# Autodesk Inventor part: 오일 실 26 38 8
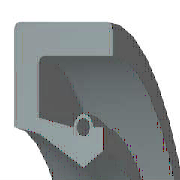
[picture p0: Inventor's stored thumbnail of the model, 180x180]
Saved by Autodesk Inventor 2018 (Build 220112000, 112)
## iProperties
IsCustomPart: 1
Created: 2012-02
Part Number: 오일 실 26 38 8
Material: 고무
Description: 오일-실
Document SubType Name: Modeling
Standard: KS B 2804
Designer: mduedu
Standards Organization: KS
Language: ko-KR
Size Designation: S - 26 38 8
Categories: <MemberInstance><Categories><Category DisplayName="샤프트 부품" InternalName="7f7aeb1f-a693-4053-b835-cee3144e0d98" Mnemonic="SHFT"><Category DisplayName="실링" Intern
Density: 0.93 g/cm^3
Appearance: 고무 - 검은색 - 버전 1.1
Author: mduedu
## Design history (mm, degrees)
revolve "본체" stored, may be unused: angle "d17" = 90 deg
revolve "스프링1" stored, may be unused: angle "d18" = 90 deg
body "Solid1"
sketch "스케치1"
  geometry: L1 (0, 19)-(8, 19); L2 (8, 19)-(8, 17.75); L3 (8, 17.75)-(1.75, 17.75); L4 (0, 19)-(0, 15.1); L5 (0, 15.1)-(1.75, 14.75); L6 (1.75, 14.75)-(4.9, 13); L7 (4.9, 13)-(0, 13); L8 (6.3, 13.875)-(6.3, 15.1); L9 (0, 0)-(9.586, 0) reference; L10 (4.9, 13)-(6.3, 13.875); L11 (0, 18)-(0, -3) reference; L12 (-1.917, 0)-(11.503, 0) reference; L13 (4.2, 15.1)-(1.75, 15.59); L14 (1.75, 15.59)-(1.75, 17.75); L15 (6.3, 15.1)-(5.6, 15.1); C1 r 0.455 at (4.9, 15.1); A1 r 0.7 centre (4.9, 15.1) between (5.6, 15.1) and (4.2, 15.1)
  constraints: 26 end point, 5 horizontal alignment, 4 perpendicular, 2 centre point, 2 collinear, 2 horizontal, 2 parallel, 2 point on circle, 2 point on line, 2 vertical alignment, 1 coincident
  dimensions: "d0" = 38 diameter of L1 L9 (= SD2); "d1" = 27.75 diameter of L8.start L9 (= ABDM); "d2" = 1.25 distance of L1.end L2.end (computed from SD); "d3" = 0.91 diameter of C1 (= SPDI); "d4" = 1.4 diameter of A1 (= SPDA); "d5" = 26 diameter of L6.end L9 (= NND); "d6" = 29.5 diameter of L5.end L9 (= TKDM); "d7" = 30.2 diameter of L4.end L9 (= HLDM); "d8" = 4.9 distance from line of C1.centre L4 (= SPDST); "d9" = 6.3 distance between parallel lines of L8 L4 (= SDI); "d10" = 8 distance between parallel lines of L2 L4 (= SWDT); "d12" = 1.75 distance between parallel lines of L14 L4 (= SD)
fillet "모깎기1" dims "d11" = 0.3 (= RR)
other parameters: "SD2" = 38 [user parameter; used in 1 equation term], "SWDT" = 8 [user parameter; used in 1 equation term], "RR" = 0.3 [user parameter; used in 1 equation term], "SD" = 1.75 [user parameter; used in 2 equation terms], "NND" = 26 [user parameter; used in 1 equation term], "SPDA" = 1.4 [user parameter; used in 1 equation term], "SPDI" = 0.91 [user parameter; used in 1 equation term], "TKDM" = 29.5 [user parameter; used in 1 equation term], "HLDM" = 30.2 [user parameter; used in 1 equation term], "ABDM" = 27.75 [user parameter; used in 1 equation term], "SDI" = 6.3 [user parameter; used in 1 equation term], "SPDST" = 4.9 [user parameter; used in 1 equation term], "d13" = 0, "d14" = 0, "d15" = 0, "LAB" = 0.35 [user parameter]
